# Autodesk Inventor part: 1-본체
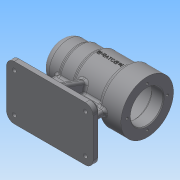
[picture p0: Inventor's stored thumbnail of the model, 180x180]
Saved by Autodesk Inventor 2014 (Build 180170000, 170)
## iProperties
Created: 2016-06
Part Number: 1-본체
Material: 일반
Document SubType Name: Modeling
Designer: 406-8
Density: 1 g/cm^3
Appearance: 기본값
Author: 406-8
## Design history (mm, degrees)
sketch "스케치1"
  geometry: L1 (46, 35)-(-46, 35); L2 (-56, 25)-(-56, -25); L3 (-46, -35)-(46, -35); L4 (56, -25)-(56, 25); L5 (56, 35)-(-56, -35); L6 (-56, 35)-(56, -35); A1 r 10 centre (46, -25) between (46, -35) and (56, -25); A2 r 10 centre (-46, -25) between (-56, -25) and (-46, -35); A3 r 10 centre (-46, 25) between (-46, 35) and (-56, 25); A4 r 10 centre (46, 25) between (56, 25) and (46, 35); 1 further point
  constraints: 12 end point, 8 point on circle, 8 point on line, 8 tangent, 4 centre point, 3 equal radius, 2 midpoint, 2 parallel, 1 horizontal, 1 perpendicular
  dimensions: "d0" = 112 distance of L6.end L5.end; "d1" = 70 distance of L5.end L6.start; "d2" = 10 radius of A1
extrude "돌출1" new body sketch "스케치1" distance "d3" = 10; taper "d4" = 0 deg
sketch "스케치2"
  geometry: A1 r 10 centre (-46, 25) between (-46, 35) and (-56, 25) reference; A2 r 10 centre (46, 25) between (56, 25) and (46, 35) reference; A3 r 10 centre (46, -25) between (46, -35) and (56, -25) reference; A4 r 10 centre (-46, -25) between (-56, -25) and (-46, -35) reference; 5 further points
  constraints: 4 coincident
hole "구멍1" sketch "스케치2" at (-46, 25), (46, 25), (46, -25), (-46, -25) diameter "d5" = 5; stored, may be unused: countersink angle "d9" = 90 deg, drill point angle "d11" = 118 deg; dims "d6" = 6, "d7" = 9, "d8" = 4, "d10" = 8
sketch "스케치3"
  geometry: L1 (-56, 70)-(56, 70); L2 (46, 0)-(-46, 0) reference; L3 (-56, 0)-(-56, 10) reference; L4 (56, 0)-(56, 10) reference; L5 (56, 70)-(56, 104); L6 (56, 104)-(28, 104); L7 (28, 104)-(28, 100); L8 (28, 100)-(-11, 100); L9 (-11, 100)-(-11, 97); L10 (-11, 97)-(-31, 97); L11 (-31, 97)-(-31, 95); L12 (-31, 95)-(-56, 95); L13 (-56, 95)-(-56, 70); L14 (56, 91)-(41, 91); L15 (41, 91)-(41, 91); L16 (38, 94)-(-10, 94); L17 (-13, 91)-(-13, 91); L18 (-13, 91)-(-24.7, 91); L19 (-25, 90.7)-(-25, 87.5); L20 (-25, 87.5)-(-42.7, 87.5); L21 (-43, 87.2)-(-43, 86); L22 (-43, 86)-(-46.7, 86); L23 (-47, 85.7)-(-47, 80.5); L24 (-47, 80.5)-(-47, 80.5); L25 (-50, 77.5)-(-50, 70); A1 r 3 centre (-47, 77.5) between (-47, 80.5) and (-50, 77.5); A2 r 0.3 centre (-46.7, 85.7) between (-46.7, 86) and (-47, 85.7); A3 r 0.3 centre (-42.7, 87.2) between (-42.7, 87.5) and (-43, 87.2); A4 r 0.3 centre (-24.7, 90.7) between (-24.7, 91) and (-25, 90.7); A5 r 3 centre (-10, 91) between (-10, 94) and (-13, 91); A6 r 3 centre (38, 91) between (41, 91) and (38, 94); 7 further points
  constraints: 44 end point, 16 parallel, 14 point on line, 12 point on circle, 12 tangent, 6 centre point, 3 equal radius, 3 perpendicular, 2 collinear, 2 vertical alignment, 1 horizontal
  dimensions: "d12" = 70 distance between parallel lines of L2 L1; "d13" = 68 diameter of L6 L1; "d14" = 60 diameter of L8 L1; "d15" = 54 diameter of L10 L1; "d16" = 50 diameter of L12 L1; "d17" = 25 distance of L11.end L12.end; "d18" = 45 horizontal distance of L9.end L12.end; "d19" = 84 horizontal distance of L7.end L12.end; "d20" = 42 diameter of L14 L1; "d21" = 48 diameter of L16 L1; "d22" = 42 diameter of L18 L1; "d23" = 35 diameter of L20 L1; "d24" = 32 diameter of L22 L1; "d25" = 21 diameter of L24 L1; "d26" = 3 distance of L23.end point (-50, 80.5); "d27" = 4 distance of L21.end point (-47, 86); "d28" = 18 distance of L19.end point (-43, 87.5); "d29" = 12 distance of L17.end point (-25, 91); "d30" = 54 distance of point (41, 94) point (-13, 94); "d31" = 15 distance of L14.start L14.end; "d43" = 3 radius of A1; "d44" = 0.3 radius of A2; "d45" = 3 radius of A5
revolve "회전1" stored, may be unused: angle "d32" = 90 deg
sketch "스케치4"
  geometry: L1 (46, 10)-(-46, 10) reference; L2 (-46, 10)-(-56, 10) reference; L3 (56, 10)-(46, 10) reference; L4 (-36, 10)-(-36, 70); L5 (-36, 70)-(36, 70); L6 (36, 70)-(36, 10); L7 (-56, 0)-(-56, 10) reference; 2 further points
  constraints: 6 end point, 3 perpendicular, 2 point on line, 1 midpoint, 1 vertical alignment
  dimensions: "d33" = 60 distance between parallel lines of L1 L5; "d35" = 20 distance between parallel lines of L4 L7
extrude "돌출2" join sketch "스케치4" stored distance "d36" = 8; taper "d37" = 0 deg
sketch "스케치5"
  geometry: L1 (10, -25)-(10, 25) reference; L2 (10, 28)-(70, 6.162); L3 (70, 6.162)-(70, -6.162); L4 (70, -6.162)-(10, -28); L5 (0, 35)-(10, 35) reference; L6 (10, 25)-(10, 35) reference; L7 (10, -35)-(10, -25) reference; L8 (10, 28)-(10, -28); L9 (10, -35)-(10, -25) reference; L10 (0, -35)-(10, -35) reference; 2 further points
  constraints: 8 end point, 2 point on line, 1 collinear, 1 equal length, 1 horizontal alignment, 1 midpoint, 1 parallel
  dimensions: "d38" = 7 distance from line of L2.start L5; "d39" = 70 distance from line of point (0, 0) L3; "d40" = 110 deg angle of L2 L6; "d68" = 7 vertical distance of L10.start L4.end (derived)
extrude "돌출3" join sketch "스케치5" stored distance "d41" = 8; taper "d42" = 0 deg
revolve "회전2" stored, may be unused: angle "d46" = 90 deg
chamfer "모따기1" distance "d47" = 1; stored, may be unused: second distance "d48" = 2, angle "d49" = 45 deg
chamfer "모따기2" distance "d50" = 4; stored, may be unused: second distance "d51" = 2, angle "d52" = 45 deg
fillet "모깎기1" dims "d53" = 3, "d54" = 10
fillet "모깎기2" dims "d55" = 3
sketch "스케치6"
  geometry: C1 r 34 at (0, 0) reference; A1 r 26 centre (0, 0) between (0, 26) and (26, 0); 3 further points
  constraints: 4 point on circle, 2 horizontal alignment, 2 vertical alignment, 1 centre point, 1 coincident
  dimensions: "d56" = 52 diameter of A1
hole "구멍2" sketch "스케치6" at (0, 26), (26, 0), (0, -26), (-26, 0) diameter "d57" = 3.242; stored, may be unused: countersink angle "d61" = 90 deg, drill point angle "d63" = 118 deg; dims "d58" = 8, "d59" = 9, "d60" = 4, "d62" = 11
sketch "스케치7"
  geometry: L1 (76.657, 104)-(102, 104) reference; L2 (0, 0)-(92, 0) reference; L3 (102, 36)-(102, 104) reference; 2 further points
  constraints: 1 other
  dimensions: "d64" = 70 vertical distance of point (46, 0) point (54, 70); "d65" = 48 distance from line of point (54, 70) L3
feature "엠보싱1" sketch "스케치7" dims "d0" = 112, "d1" = 70, "d2" = 10, "d66" = 0.5, "d67" = 0
node "솔리드1"
